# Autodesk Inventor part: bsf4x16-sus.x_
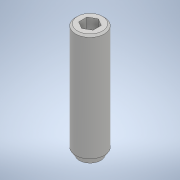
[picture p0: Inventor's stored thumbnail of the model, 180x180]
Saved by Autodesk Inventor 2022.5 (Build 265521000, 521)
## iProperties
Created: 2020-01
Part Number: bsf4x16-sus.x_
Material: 一般
Document SubType Name: Modeling
Designer: ImaoCorp
Density: 1 g/cm^3
Appearance: 既定
Sending System: SOLIDWORKS 2018-2018316
MC: AMD64
MC_MODEL: Intel64 Family 6 Model 60 Stepping 3, GenuineIntel
OS: Windows_NT
FRU: Parasolid Version 30.0, build 310,  6- 8-2018
FORMAT: text
GUISE: transmit
KEY: bsf4x16-sus
FILE: bsf4x16-sus.x_t
DATE: Thu Jan 23 16:48:54 2020
Author: ImaoCorp
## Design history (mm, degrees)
feature "Base1"
node "ソリッド1"
